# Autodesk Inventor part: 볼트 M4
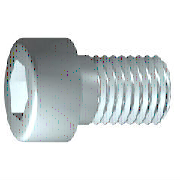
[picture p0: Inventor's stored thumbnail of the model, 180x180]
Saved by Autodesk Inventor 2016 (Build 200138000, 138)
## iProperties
IsCustomPart: 0
Created: 2012-02
Part Number: 볼트 M4
Material: 스테인리스강
Description: 6각 소켓 머리 캡 나사
Document SubType Name: Modeling
Standard: ISO 4762
Designer: mduedu
Standard Revision: Fourth edition 2004-03-01
Standards Organization: ISO
Language: ko-KR
Size Designation: M4 x 12
Categories: <MemberInstance><Categories><Category DisplayName="조임쇠" InternalName="e4da775c-781d-43d5-af7c-5136215cf5a6" Mnemonic="FSTN"><Category DisplayName="볼트" InternalN
Density: 7.75 g/cm^3
Appearance: 반광택
Author: mduedu
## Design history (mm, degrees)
sketch "스케치1"
  geometry: L1 (-1, 0)-(12, 0); L2 (12, 0)-(12, 2); L3 (12, 2)-(1.75, 2); L4 (1.75, 2)-(1.32, 2); L5 (1.32, 2)-(0, 2); L6 (0, 2)-(0, 3.5); L7 (0, 3.5)-(-4, 3.5); L8 (-4, 3.5)-(-4, 1.732); L9 (-4, 1.732)-(-2, 1.732); L10 (-2, 1.732)-(-1, 0); L11 (-7.2, 0)-(15.2, 0) reference; L12 (0, -0.7)-(0, 4.2) reference; L13 (1.75, 2)-(0, 2)
  constraints: 22 end point, 6 parallel, 2 collinear, 2 perpendicular, 1 horizontal, 1 point on line
  dimensions: "d1" = 10.25 distance from line of L3.end L2 (= GEL); "d2" = 0.42952 distance of L4.end L3.end (computed from GAL); "d3" = 4 distance between parallel lines of L8 L6 (= KOH); "d4" = 2 distance of L8.end L9.end (= INTI); "d5" = 60 deg angle of L10 L1; "d6" = 4 diameter of L3 L1 (= GD); "d7" = 4 diameter of L5 L1 (= BDM); "d8" = 3.4641 diameter of L9 L1 (= 1.1547 x SW); "d9" = 7 diameter of L7 L1 (= KOD); "d26" = 12 distance between parallel lines of L12 L2 (= NLG)
revolve "본체" sketch "스케치1" stored, may be unused: angle "d10" = 90 deg
sketch "스케치2"
  geometry: L1 (0, -4.9)-(0, 4.9) reference; L2 (-4.9, 0)-(4.9, 0) reference; L3 (1.732, 0)-(0.866, -1.5); L4 (0.866, -1.5)-(-0.866, -1.5); L5 (-0.866, -1.5)-(-1.732, 0); L6 (-1.732, 0)-(-0.866, 1.5); L7 (-0.866, 1.5)-(0.866, 1.5); L8 (0.866, 1.5)-(1.732, 0); 2 further points
  constraints: 12 end point, 1 coincident, 1 horizontal alignment, 1 point on line, 12 other
extrude "슬롯" join sketch "스케치2" stored distance "d11" = 10; taper "d12" = 0 deg
workplane "Work Plane1"
fillet "Fillet2" dims "d30" = 0.1 (= R)
body "Solid1"
fillet "모깎기1" dims "d17" = 0.4 (= RR)
feature "스레드" dims "d13" = 10.25 (= GEL), "d14" = 0
chamfer "모따기1" distance "d15" = 0.42941 (= -0.5 x SPD + 0.5 x GD); stored, may be unused: second distance "d16" = 0.42941 (= GUL), angle "d27" = 45 deg
other parameters: "GD" = 4 [user parameter; used in 2 equation terms], "NLG" = 12 [user parameter; used in 1 equation term], "GEL" = 10.25 [user parameter; used in 2 equation terms], "KOD" = 7 [user parameter; used in 1 equation term], "KOH" = 4 [user parameter; used in 1 equation term], "INTI" = 2 [user parameter; used in 1 equation term], "GAL" = 0.42941 (= 0.61345 x PTC) [user parameter; used in 1 equation term], "GUL" = 0.42941 (= 0.61345 x PTC) [user parameter; used in 1 equation term], "BDM" = 4 (= NND) [user parameter; used in 1 equation term], "SW" = 3 [user parameter; used in 2 equation terms], "RR" = 0.4 [user parameter; used in 1 equation term], "SPD" = 3.14117 (= NND - 1.2269 x PTC) [user parameter; used in 1 equation term], "d19" = 0, "d28" = 0, "d29" = 0, "R" = 0.1 [user parameter; used in 1 equation term], "TOA" = 30 deg [user parameter], "GD1" = 3.14117 (= THREADDIA - 1.2269 x PTC) [user parameter], "THREADDIA" = 4 [user parameter; used in 1 equation term], "FAWI" = 45 deg [user parameter], "TPU" = 14.28571 (computed from PTC) [user parameter], "PTC" = 0.7 [user parameter; used in 5 equation terms], "NND" = 4 [user parameter; used in 2 equation terms], "E0" = 3.465 (= 1.155 x SW) [user parameter]
